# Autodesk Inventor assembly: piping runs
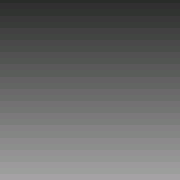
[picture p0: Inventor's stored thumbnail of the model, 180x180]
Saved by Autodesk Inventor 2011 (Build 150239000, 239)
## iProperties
ActiveState: False
BendRadius: UnInitValue
CouplingKey: v3#12b64993-10e6-4915-8315-0c0cce209ad0#8
DefaultBendRadius: UnInitValue
Diameter: M40
DiameterType: Nominal
Elbow45Key: v3#28e76e79-e22c-40ab-8be2-ff545b1407c5#8
Elbow90Key: v3#1f65ece3-c41a-48d4-8661-909ed34ade86#8
ElbowCustomKey: UnInitValue
EndFittingKey: UnInitValue
Ending: UnInitValue
FittingMaterial: UnInitValue
FittingStandard: UnInitValue
FlangeKey: UnInitValue
Gap: UnInitValue
GasketKey: UnInitValue
ID: UnInitValue
IntermediateSegmentsInc: 1,000 mm
IntermediateSegmentsMax: 5000,000 mm
IntermediateSegmentsMin: 60,000 mm
IsButtWelded: False
IsFlanged: False
IsSelfDraining: False
Material: UnInitValue
MixedUnits: False
Name: JIS G 3458/JIS B 2316 -  Tuyau et fixations en acier soudé
OD: UnInitValue
PipeKey: v3#da14b0ab-0b36-4851-8d66-8c9cd0bcbe86#23
PipeType: Rigid Pipe
PipingComponentColor: As Material
RoundUpValue: UnInitValue
RouteDirection45: True
RouteDirection90: True
Schedule: 80
ShowGap: UnInitValue
Standard: UnInitValue
StartFittingKey: UnInitValue
SuppressEndFitting: UnInitValue
SuppressStartFitting: UnInitValue
TerminationSegmentsInc: 1,000 mm
TerminationSegmentsMax: 5000,000 mm
TerminationSegmentsMin: 60,000 mm
UseFlangsForCouplings: UnInitValue
UseSubASM: UnInitValue
_ComponentInfo: <CS><C N="Pipe" R="2.430000" IR="1.920000" PL="PL" PN="JIS G 3458 Pipe 40 A x Sch 80"><CO N="1"><FE V="0"/><FD V="1"/><ET V="Welded"/><NS V="M40"/><MA V="0.0000
ActiveState: True
CouplingKey: v3#52ad3977-2b89-4007-a6a6-7626bac0ae85#4
Diameter: 1/2
Elbow45Key: v3#5c2ab816-abcb-49a6-a106-4733af000f51#4
Elbow90Key: v3#160eac10-3e6f-4b5c-839c-61eee0d373dc#4
IntermediateSegmentsInc: 2,540 mm
IntermediateSegmentsMax: 5080,000 mm
IntermediateSegmentsMin: 50,800 mm
Name: ASME B36.10M-ASME B16.11 - Tuyau en acier fileté
PipeKey: v3#4a736116-503a-44ad-a922-868ac6b46736#1
Schedule: 30
TerminationSegmentsInc: 2,540 mm
TerminationSegmentsMax: 5080,000 mm
TerminationSegmentsMin: 50,800 mm
_ComponentInfo: <CS><C N="Pipe" R="1.066800" IR="0.825500" PL="PL" PN="ASME B36.10M Pipe with Threaded Ends 1/2 - Schedule 30"><CO N="1"><FE V="0"/><FD V="1"/><ET V="Threaded"/
CouplingKey: v3#ed415c76-4cec-44a3-ba67-72e47bf70384#4
Elbow45Key: v3#2e5fd082-3851-4eb0-bde1-6c7078a7d72b#4
Elbow90Key: v3#82a08401-12d7-413b-b7f9-9cf3b607be7b#4
IntermediateSegmentsMin: 25,400 mm
Name: ASTM A53/A53M-ASME B16.11 - Tuyau en acier soudé
PipeKey: v3#4ce5e9fa-6da0-4801-ac02-ee7a0fb518d6#7
Schedule: 40
TerminationSegmentsMin: 25,400 mm
_ComponentInfo: <CS><C N="Pipe" R="1.066800" IR="0.789940" PL="PL" PN="ASTM A 53/A 53M Pipe 1/2 - Schedule 40"><CO N="1"><FE V="0"/><FD V="0"/><ET V="Welded"/><NS V="1/2"/><MA 
CouplingKey: v3#7e56b2cb-a132-4546-b8a7-a14538454b94#3
Elbow45Key: v3#a96c5204-26e4-4bb2-b8f1-f0623fbc94bb#2
Elbow90Key: v3#b72bb08b-ad33-47cc-a03d-7f3d76c6616b#3
Name: ISO 7598/ISO 49 - Tuyau et fixations en acier fileté avec fixations en fer
PipeKey: v3#1052637f-74b5-47f4-adeb-d4e8d3fa53b8#1
Schedule: ID=16.1
_ComponentInfo: <CS><C N="Pipe" R="1.065000" IR="0.805000" PL="PL" PN="ISO 7598 Tube with Threaded Ends DN15"><CO N="1"><FE V="0"/><FD V="1"/><ET V="Threaded"/><NS V="1/2"/><MA
Angle: 92,00 deg
CouplingKey: UnInitValue
Diameter: 1
Elbow45Key: v3#bf26aa2a-f3dd-474c-8758-922a145c2b02#15
Elbow90Key: v3#3e93288f-9bb7-4e46-9d6b-544f8c20ca1c#3
ElbowCustomKey: v3#1f3bd44a-47ab-42f9-b3e0-74afa0c3f0ca#3
Gap: 2,388 mm
IntermediateSegmentsInc: 0.00001 in
IsButtWelded: True
IsSelfDraining: True
Name: ASTM A 53/A-ASME B16.9 - ASME BPE - Soudé bout à bout
PipeKey: v3#b10c956f-6fc6-429e-8056-0864a8581764#35
Schedule: ID=0.87
ShowGap: True
TerminationSegmentsInc: 0.00001 in
_ComponentInfo: <CS><C N="Pipe" R="1.270000" OR="1.270000" IR="1.104900" PL="PL" PartType="pipe" SymKey="" PN="ASTM A 269 Tube with Welded ends 1 x 0.87"><CO N="1"><FE V="2"/><
Angle: UnInitValue
BendRadius: 12,700 mm
Elbow45Key: UnInitValue
Elbow90Key: UnInitValue
ID: 1,27
IntermediateSegmentsInc: UnInitValue
IntermediateSegmentsMax: UnInitValue
IntermediateSegmentsMin: UnInitValue
IsButtWelded: UnInitValue
IsFlanged: UnInitValue
IsSelfDraining: UnInitValue
MixedUnits: UnInitValue
Name: Tuyau flexible hydraulique - Aucune fixation
OD: 2,2352
PipeKey: v3#d489867e-ac9b-47ea-b952-0a1b885f66be#4
PipeType: Flexible Hose
RoundUpValue: 3,175 mm
RouteDirection45: UnInitValue
RouteDirection90: UnInitValue
Schedule: ID=0.5
SuppressEndFitting: True
SuppressStartFitting: True
TerminationSegmentsInc: UnInitValue
TerminationSegmentsMax: UnInitValue
TerminationSegmentsMin: UnInitValue
UseSubASM: True
_ComponentInfo: <CS><C N="Pipe" R="1.117600" OR="1.117600" IR="0.635000" PL="PL" PartType="" SymKey="" PN="Parker Hydraulic Hose - No Skive 1/2"><CO N="1"><FE V="0"/><FD V="0"/
CouplingKey: v3#181262db-c004-4877-bc40-c64b931a44f6#3
Elbow45Key: v3#960407aa-00b9-4d72-aae7-d50595845cfd#3
Elbow90Key: v3#6c92b367-65e9-486b-b952-db434ae2548d#3
IntermediateSegmentsMin: 20,000 mm
Name: JIS G 3442/JIS B 2301 - Tuyau en acier fileté et fixations en fer
PipeKey: v3#9964fba4-9d5a-4d75-85a8-e38022ccdce1#2
TerminationSegmentsMin: 20,000 mm
_ComponentInfo: <CS><C N="Pipe" R="1.085000" IR="0.805000" PL="PL" PN="JIS G 3442 Pipe with Threaded Ends 21.7 x 2.8"><CO N="1"><FE V="0"/><FD V="1"/><ET V="Threaded"/><NS V="1
CouplingKey: v3#eaa8de87-dc67-4eca-ba7e-4267a30f8f7f#2
Elbow45Key: v3#2769403e-a4fd-4a4c-8e4c-659ea845bd78#2
Elbow90Key: v3#c4513a61-3106-4a78-baf9-a1badd100245#2
IntermediateSegmentsMax: 2500,000 mm
Name: JIS K 6741/JIS K 6739 - Tuyau et fixations articulés en PVC-U
PipeKey: v3#45338dd0-af69-48c0-a2ed-8ade33a08701#5
Schedule: VP
TerminationSegmentsMax: 2500,000 mm
_ComponentInfo: <CS><C N="Pipe" R="2.400000" IR="2.040000" PL="PL" PN="JIS K 6741 Pipe VP 40"><CO N="1"><FE V="0"/><FD V="1"/><ET V="Jointed"/><NS V="M40"/><MA V="4.000000"/><M
CouplingKey: v3#771d4942-b9e7-43bc-9d41-ab12a9580492#3
Elbow45Key: v3#626cc28c-1a24-4045-be0d-40d896dc828d#3
Elbow90Key: v3#bc6b44ab-9235-4590-b699-74498030a1ff#3
Name: ANSI/ASME B36.19M-ASME B16.3 - Tuyau fileté avec fixations en fer
PipeKey: v3#323c0148-c750-449d-a0c6-11721f2a5046#1
Schedule: 40S
_ComponentInfo: <CS><C N="Pipe" R="1.066800" IR="0.789940" PL="PL" PN="ANSI/ASME B36.19M Pipe with Threaded Ends 1/2 - Schedule 40S"><CO N="1"><FE V="0"/><FD V="1"/><ET V="Thre
Diameter: 6
Elbow90Key: v3#97ecdcaf-8aa3-4fb0-8b6a-3da783de2ad5#108
Gap: 1,575 mm
IntermediateSegmentsMin: 76,200 mm
Name: ASTM A 53/A-ASME B16.9 - Tuyau en acier soudé bout à bout
PipeKey: v3#4ce5e9fa-6da0-4801-ac02-ee7a0fb518d6#77
RouteDirection45: False
TerminationSegmentsMin: 76,200 mm
_ComponentInfo: <CS><C N="Elbow90" ER="15.240000" S1="15.240000" S2="15.240000" D1="0.000000" D2="0.000000" PartType="fitting" SymKey="ELBW"><CO N="1"><FE V="2"/><FD V="0"/><ET
Elbow45Key: v3#81684a3f-f2a4-4fe6-95b1-f067ddead22f#1
Elbow90Key: v3#451ae64e-c79d-4cba-b533-c09b8090ecb2#1
IntermediateSegmentsInc: 10,000 mm
IntermediateSegmentsMax: 9000,000 mm
IntermediateSegmentsMin: 1000,000 mm
Name: ISO 2531 - Tuyau et fixations à bride en fonte ductile
PipeKey: v3#f52fbdcb-ece8-4303-8b76-5dbe8c7f2f9c#16
Schedule: PN10
TerminationSegmentsInc: 10,000 mm
TerminationSegmentsMax: 9000,000 mm
TerminationSegmentsMin: 1000,000 mm
_ComponentInfo: <CS><C N="Pipe" R="2.700000" IR="2.000000" PL="PL" PN="ISO 2531 Pipe with Integrally Cast Flanges DN40 PN 10"><CO N="1"><FE V="0"/><FD V="0"/><ET V="Flanged"/><
CouplingKey: v3#3edf83e2-464b-4b31-84c5-c329ffbf2a4f#5
Elbow45Key: v3#2f597a97-b15b-49d4-87cb-7bfe69eb62ee#5
Elbow90Key: v3#fbd68fd5-590c-4cb5-8c20-9e9bdd396a04#5
Name: DIN 8062/DIN 8063 - Tuyau et fixations articulés en PVC-U
PipeKey: v3#3d294dc7-89c3-4c37-a0ae-28c15a73bfd0#13
Schedule: 5
_ComponentInfo: <CS><C N="Pipe" R="2.000000" IR="1.700000" PL="PL" PN="DIN 8062 Pipe 40 x 3"><CO N="1"><FE V="0"/><FD V="0"/><ET V="Jointed"/><NS V="M40"/><MA V="8.000000"/><MI
Elbow45Key: v3#97879d80-057e-491b-840b-74a9b3a7cf63#17
Elbow90Key: v3#ace818b0-7b7c-4ad9-b19c-6da358a202c1#17
Name: DIN 2458/DIN 2605 - Tuyau et fixations en acier soudé
PipeKey: v3#dcef2839-8903-4c98-a96c-b861f5d9bb7f#98
Schedule: ID=30.7
_ComponentInfo: <CS><C N="Pipe" R="2.415000" IR="1.535000" PL="PL" PN="DIN 2458 Pipe 48.3 x 8.8"><CO N="1"><FE V="2"/><FD V="0"/><ET V="Welded"/><NS V="M40"/><MA V="0.000000"/>
EndFittingKey: v3#b50cb43e-68c0-48ac-8e25-7ef224ce0e6c#3
Name: Tuyau flexible hydraulique - Filetage droit mâle
StartFittingKey: v3#b50cb43e-68c0-48ac-8e25-7ef224ce0e6c#3
SuppressEndFitting: False
SuppressStartFitting: False
EndFittingKey: v3#c8250148-a7b6-458b-b7bd-3b56763ca7cc#13
Name: Tuyau flexible hydraulique - Filetage conique mâle
StartFittingKey: v3#c8250148-a7b6-458b-b7bd-3b56763ca7cc#13
EndFittingKey: v3#c5e461f5-5e73-4f2e-8c1e-4358d4d6f46c#4
Name: Tuyau flexible hydraulique - Filetage femelle - Joint articulé
StartFittingKey: v3#c5e461f5-5e73-4f2e-8c1e-4358d4d6f46c#4
Elbow90Key: v3#6a678020-d9d9-4685-bba9-906b9a167083#10
FlangeKey: v3#c11442d2-c568-438f-a870-8ac9b5b636cb#10
GasketKey: v3#2a41914c-f5fb-4682-9c6a-1870d826d3d0#23
IsFlanged: True
Name: ASTM A 53/A-ASME B16.5 - Tuyau taraudé en acier à brides
PipeKey: v3#c5bd7d28-cdb3-4507-9f3d-c2787d93fe8a#40
_ComponentInfo: <CS><C N="Elbow90" ER="21.590000" S1="21.590000" S2="21.590000" D1="0.000000" D2="0.000000" PartType="fitting" SymKey="ELFL"><CO N="1"><FE V="2"/><FD V="1"/><ET
CouplingKey: v3#0dc1ae02-7bbf-4ccf-8498-581434b0a765#3
DefaultBendRadius: 50,800 mm
IntermediateSegmentsMax: 2540,000 mm
IntermediateSegmentsMin: 0,000 mm
Name: ASTM B 88-ASME B16.22 - Tuyau en cuivre brasé
PipeKey: v3#44b182c9-4bce-4825-bb4d-596143122252#7
PipeType: Tubing
Schedule: L
TerminationSegmentsMax: 2540,000 mm
TerminationSegmentsMin: 0,000 mm
_ComponentInfo: <CS><C N="Pipe" R="0.793750" IR="0.692150" PL="PL" PN="ASTM B 88 Tube 1/2 - Type L"><CO N="1"><FE V="0"/><FD V="0"/><ET V="Soldered"/><NS V="1/2"/><MA V="2.5400
Created: 2006-09
Part Number: piping runs
Document SubType Name: Tube & Pipe
Designer: Autodesk
Manufacturer: Standard
Standards Organization: Custom
CouplingKey: v3#b06656e5-2b55-488c-bcf0-6a90c79c4683#2
Elbow45Key: v3#421a8b99-1721-409a-bc3b-c00889561754#1
Elbow90Key: v3#17490b17-1dd8-40fc-8de7-1a70c3bab2d7#1
Name: ISO 4065-ISO 3633 - Tuyaux et fixations en PVC
PipeKey: v3#4f84f716-5ba0-45ef-967a-c32c3d7345ce#70
Schedule: S40
_ComponentInfo: <CS><C N="Pipe" R="2.000000" IR="1.950000" PL="PL" PN="ISO 4065 Pipe 40 x 0.5 S40"><CO N="1"><FE V="0"/><FD V="0"/><ET V="Jointed"/><NS V="M40"/><MA V="6.000000
CouplingKey: v3#29993622-4c6a-437e-8b8c-43a0846f8735#1
Elbow45Key: v3#d7b5d569-4a12-4d65-ba55-12203d6ac7ed#1
Elbow90Key: v3#25d2a8db-6517-4627-a5a4-9d27e4d26b9b#1
Name: ASTM D 1785-ASTM D 2466 - Tuyau et fixations articulés en PVC
PipeKey: v3#4bf12049-4375-491b-8f13-d4ee0c517c57#1
_ComponentInfo: <CS><C N="Pipe" R="1.066800" IR="0.789940" PL="PL" PN="ASTM D 1785 Pipe 1/2 - Schedule 40"><CO N="1"><FE V="0"/><FD V="0"/><ET V="Jointed"/><NS V="1/2"/><MA V="
EndFittingKey: v3#cc3bd835-95a2-497d-9893-176cd9c426f6#7
Name: Tuyau flexible hydraulique - Filetage conique femelle
StartFittingKey: v3#cc3bd835-95a2-497d-9893-176cd9c426f6#7
FlangeKey: v3#24991861-26e3-4c21-a713-f46e314eddd5#10
Name: ASTM A 53/A 53M - Tuyau en acier à collet/soudé bout à bout
UseFlangsForCouplings: False
_ComponentInfo: <CS><C N="Pipe" R="8.413750" OR="8.413750" IR="7.702550" PL="PL" PartType="pipe" SymKey="" PN="ASTM A 53/A 53M Pipe 6 - Schedule 40"><CO N="1"><FE V="2"/><FD V=
EndFittingKey: v3#933069c9-73b6-4141-af99-628d4a97b2c2#1
Name: Tuyau flexible hydraulique - Connexion à brides SAE
StartFittingKey: v3#933069c9-73b6-4141-af99-628d4a97b2c2#1
count: 53
Refkey_Axis1_Context: 2|0|0|0|1|0|0|0|
Refkey_Axis1: 6|0|0|0|44|0|0|0|78|0|65|0|77|0|69|0|83|0|10|0|67|0|111|0|108|0|111|0|114|0|115|0|10|0|49|0|58|0|10|0|10|0|69|0|78|0|68|0|10|0|0|0|
Refkey_Axis2_Context: 2|0|0|0|1|0|0|0|
Refkey_Axis2: 6|0|0|0|88|0|0|0|78|0|65|0|77|0|69|0|83|0|10|0|67|0|111|0|108|0|111|0|114|0|115|0|10|0|49|0|58|0|82|0|111|0|117|0|116|0|101|0|32|0|85|0|73|0|32|0|84|0|111|0|111
Refkey_Axis3_Context: 2|0|0|0|1|0|0|0|
Refkey_Axis3: 6|0|0|0|88|0|0|0|78|0|65|0|77|0|69|0|83|0|10|0|67|0|111|0|108|0|111|0|114|0|115|0|10|0|49|0|58|0|82|0|111|0|117|0|116|0|101|0|32|0|85|0|73|0|32|0|84|0|111|0|111
Refkey_Ext_Context: 2|0|0|0|1|0|0|0|
Refkey_Ext: 6|0|0|0|92|0|0|0|78|0|65|0|77|0|69|0|83|0|10|0|67|0|111|0|108|0|111|0|114|0|115|0|10|0|49|0|58|0|82|0|111|0|117|0|116|0|101|0|32|0|85|0|73|0|32|0|84|0|111|0|111
Refkey_Snap_Context: 2|0|0|0|1|0|0|0|
Refkey_Snap: 6|0|0|0|84|0|0|0|78|0|65|0|77|0|69|0|83|0|10|0|67|0|111|0|108|0|111|0|114|0|115|0|10|0|49|0|58|0|82|0|111|0|117|0|116|0|101|0|32|0|85|0|73|0|32|0|84|0|111|0|111
CouplingKey: v3#d2599e7a-1865-48da-a234-5418a1cd5dfe#3
Elbow45Key: v3#6ce5b1be-37aa-4928-b23a-0df64e6ddf38#2
Elbow90Key: v3#9fba244e-81ed-4fc6-a9ac-7eb372fa3ffe#3
Name: DIN 2458/DIN EN 10242 - Tuyau en acier fileté et fixations en fer
PipeKey: v3#d689fd5f-ac5a-46d7-a883-3089b2f6e0a4#28
Schedule: ID=12.3
_ComponentInfo: <CS><C N="Pipe" R="1.065000" IR="0.615000" PL="PL" PN="DIN 2458 Pipe with Threaded Ends 21.3 x 4.5"><CO N="1"><FE V="0"/><FD V="1"/><ET V="Threaded"/><NS V="1/2
Author: Autodesk
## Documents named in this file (1)
- D:\Template\FRA\piping runs.iam
